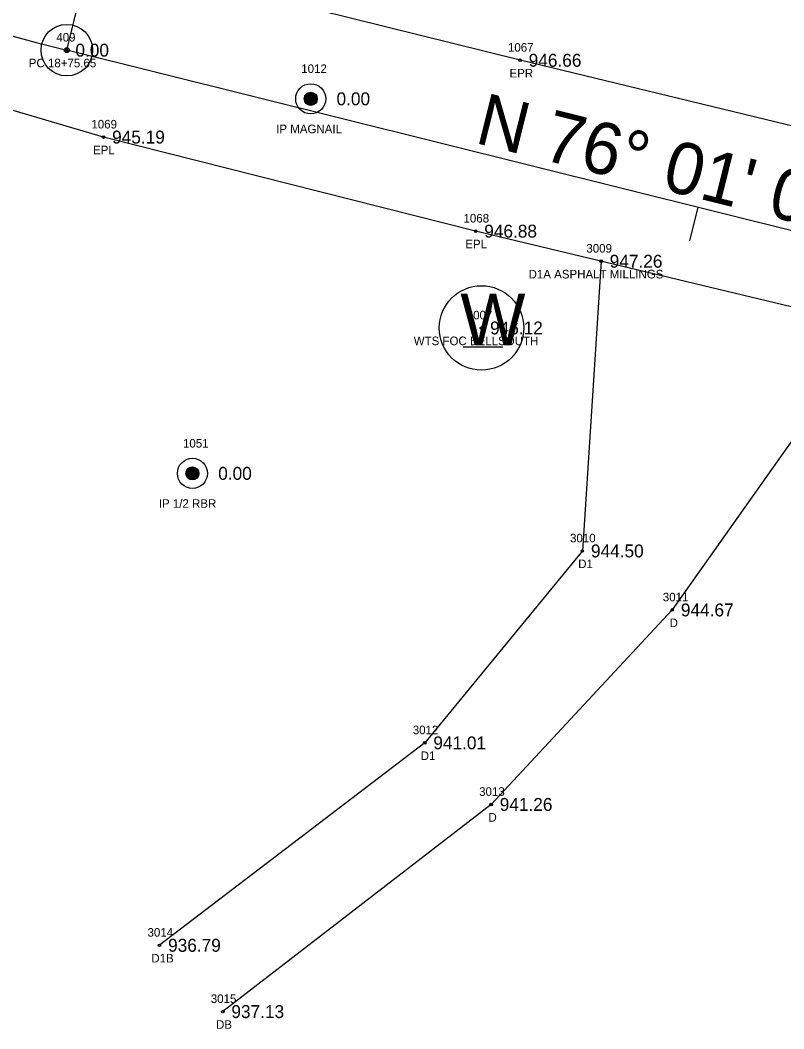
# Model space of a CAD drawing. Extents: x 1528109 to 1531398, y 1157799 to 1162548.
# Drawn here: x 1530236 to 1530324.8, y 1159054.3 to 1159171.6 of the extents above; entities that cross this region are included whole.
import ezdxf

# ---------------------------------------------------------------- set-up
doc = ezdxf.new("R2010")
doc.units = 0
for name, color, linetype in [('RD_EX_Driveway', 7, 'Continuous'), ('RD_EX_Driveway_txCode', 7, 'Continuous'), ('RD_EX_DV_Prop_txCode', 7, 'Continuous'), ('RD_EX_DV_PropPin', 7, 'Continuous'), ('RD_EX_Road', 7, 'Continuous'), ('RD_EX_Road_txCode', 7, 'Continuous'), ('RD_EX_TX_Driveway_ELEV', 7, 'Continuous'), ('RD_EX_TX_DV_Prop_ELEV', 7, 'Continuous'), ('RD_EX_TX_Road_ELEV', 7, 'Continuous'), ('RD_EX_TX_UT_ELEV', 7, 'Continuous'), ('RD_EX_UT', 7, 'Continuous'), ('RD_EX_UT_txCode', 7, 'Continuous'), ('RD_HC_Cl', 7, 'Continuous'), ('RD_HC_Data', 7, 'Continuous'), ('RD_HC_Data_Tic', 7, 'Continuous'), ('RD_HC_Survey_ELEV', 7, 'Continuous'), ('RD_HC_txCode', 7, 'Continuous'), ('RD_SMD_Locator', 7, 'Continuous')]:
    doc.layers.add(name, color=color, linetype=linetype)

msp = doc.modelspace()

# ---------------------------------------------------------------- linework, layer by layer
at = {"layer": 'RD_EX_Driveway'}
for points in [[(1530303.55, 1159143.56), (1530301.37, 1159109.87), (1530283.04, 1159087.55), (1530252.19, 1159064.01)], [(1530335.11, 1159135.94), (1530311.83, 1159103.01), (1530290.76, 1159080.39), (1530259.55, 1159056.3)]]:
    msp.add_lwpolyline(points, dxfattribs=at)
at = {"layer": 'RD_EX_DV_PropPin'}
for p, q in [((1530269.36, 1159161.81), (1530269.36, 1159163.08)), ((1530269.39, 1159161.79), (1530269.39, 1159163.1)), ((1530269.43, 1159161.77), (1530269.43, 1159163.12)), ((1530269.46, 1159161.75), (1530269.46, 1159163.14)), ((1530269.5, 1159161.74), (1530269.5, 1159163.16)), ((1530269.53, 1159161.73), (1530269.53, 1159163.17)), ((1530269.57, 1159161.72), (1530269.57, 1159163.18)), ((1530269.6, 1159161.71), (1530269.6, 1159163.19)), ((1530269.64, 1159161.7), (1530269.64, 1159163.2)), ((1530269.67, 1159161.69), (1530269.67, 1159163.2)), ((1530269.71, 1159161.69), (1530269.71, 1159163.21)), ((1530269.74, 1159161.69), (1530269.74, 1159163.21)), ((1530269.78, 1159161.69), (1530269.78, 1159163.21)), ((1530269.81, 1159161.69), (1530269.81, 1159163.21)), ((1530269.85, 1159161.69), (1530269.85, 1159163.21)), ((1530269.88, 1159161.69), (1530269.88, 1159163.2)), ((1530269.92, 1159161.7), (1530269.92, 1159163.2)), ((1530269.95, 1159161.71), (1530269.95, 1159163.19)), ((1530269.99, 1159161.72), (1530269.99, 1159163.18)), ((1530270.02, 1159161.73), (1530270.02, 1159163.17)), ((1530270.06, 1159161.74), (1530270.06, 1159163.16)), ((1530270.09, 1159161.75), (1530270.09, 1159163.14)), ((1530270.13, 1159161.77), (1530270.13, 1159163.12)), ((1530270.16, 1159161.79), (1530270.16, 1159163.1)), ((1530270.2, 1159161.81), (1530270.2, 1159163.08)), ((1530269.04, 1159162.25), (1530269.04, 1159162.64)), ((1530269.08, 1159162.15), (1530269.08, 1159162.75)), ((1530269.11, 1159162.08), (1530269.11, 1159162.82)), ((1530269.15, 1159162.02), (1530269.15, 1159162.87)), ((1530269.18, 1159161.97), (1530269.18, 1159162.92)), ((1530269.22, 1159161.93), (1530269.22, 1159162.96)), ((1530269.25, 1159161.9), (1530269.25, 1159163)), ((1530269.29, 1159161.87), (1530269.29, 1159163.03)), ((1530269.32, 1159161.84), (1530269.32, 1159163.06)), ((1530270.23, 1159161.84), (1530270.23, 1159163.06)), ((1530270.27, 1159161.87), (1530270.27, 1159163.03)), ((1530270.3, 1159161.9), (1530270.3, 1159163)), ((1530270.34, 1159161.93), (1530270.34, 1159162.96)), ((1530270.37, 1159161.97), (1530270.37, 1159162.92)), ((1530270.41, 1159162.02), (1530270.41, 1159162.87)), ((1530270.44, 1159162.08), (1530270.44, 1159162.82)), ((1530270.48, 1159162.15), (1530270.48, 1159162.75)), ((1530270.51, 1159162.25), (1530270.51, 1159162.64)), ((1530255.29, 1159118.7), (1530255.29, 1159119.09)), ((1530255.32, 1159118.59), (1530255.32, 1159119.19)), ((1530255.36, 1159118.52), (1530255.36, 1159119.26)), ((1530255.39, 1159118.46), (1530255.39, 1159119.32)), ((1530255.43, 1159118.42), (1530255.43, 1159119.37)), ((1530255.46, 1159118.38), (1530255.46, 1159119.41)), ((1530255.5, 1159118.34), (1530255.5, 1159119.44)), ((1530255.53, 1159118.31), (1530255.53, 1159119.47)), ((1530255.57, 1159118.28), (1530255.57, 1159119.5)), ((1530255.6, 1159118.26), (1530255.6, 1159119.53)), ((1530255.64, 1159118.24), (1530255.64, 1159119.55)), ((1530255.67, 1159118.22), (1530255.67, 1159119.57)), ((1530255.71, 1159118.2), (1530255.71, 1159119.58)), ((1530255.74, 1159118.18), (1530255.74, 1159119.6)), ((1530255.78, 1159118.17), (1530255.78, 1159119.61)), ((1530255.81, 1159118.16), (1530255.81, 1159119.62)), ((1530255.85, 1159118.15), (1530255.85, 1159119.63)), ((1530255.88, 1159118.14), (1530255.88, 1159119.64)), ((1530255.92, 1159118.14), (1530255.92, 1159119.65)), ((1530255.95, 1159118.13), (1530255.95, 1159119.65)), ((1530255.99, 1159118.13), (1530255.99, 1159119.65)), ((1530256.02, 1159118.13), (1530256.02, 1159119.65)), ((1530256.06, 1159118.13), (1530256.06, 1159119.65)), ((1530256.09, 1159118.13), (1530256.09, 1159119.65)), ((1530256.13, 1159118.14), (1530256.13, 1159119.65)), ((1530256.16, 1159118.14), (1530256.16, 1159119.64)), ((1530256.2, 1159118.15), (1530256.2, 1159119.63)), ((1530256.23, 1159118.16), (1530256.23, 1159119.62)), ((1530256.27, 1159118.17), (1530256.27, 1159119.61)), ((1530256.3, 1159118.18), (1530256.3, 1159119.6)), ((1530256.34, 1159118.2), (1530256.34, 1159119.58)), ((1530256.37, 1159118.22), (1530256.37, 1159119.57)), ((1530256.41, 1159118.24), (1530256.41, 1159119.55)), ((1530256.44, 1159118.26), (1530256.44, 1159119.53)), ((1530256.48, 1159118.28), (1530256.48, 1159119.5)), ((1530256.51, 1159118.31), (1530256.51, 1159119.47)), ((1530256.55, 1159118.34), (1530256.55, 1159119.44)), ((1530256.58, 1159118.38), (1530256.58, 1159119.41)), ((1530256.62, 1159118.42), (1530256.62, 1159119.37)), ((1530256.65, 1159118.46), (1530256.65, 1159119.32)), ((1530256.69, 1159118.52), (1530256.69, 1159119.26)), ((1530256.72, 1159118.59), (1530256.72, 1159119.19)), ((1530256.76, 1159118.7), (1530256.76, 1159119.09))]:
    msp.add_line(p, q, dxfattribs=at)
for centre, radius in [((1530269.78, 1159162.45), 1.75), ((1530269.78, 1159162.45), 0.761), ((1530256.02, 1159118.89), 1.75), ((1530256.02, 1159118.89), 0.761)]:
    msp.add_circle(centre, radius, dxfattribs=at)
at = {"layer": 'RD_EX_Road'}
for points in [[(1530337.52, 1159156.44), (1530294.13, 1159166.93), (1530250.93, 1159177.7), (1530204.42, 1159191.5), (1530168.45, 1159204.97), (1530120.58, 1159231.54), (1530104.56, 1159243.15), (1530086.77, 1159257.61), (1530051.98, 1159290.88), (1530019.2, 1159326.18), (1529978.15, 1159378.31), (1529959.68, 1159408.2), (1529942.81, 1159442.34), (1529934.79, 1159460.88), (1529923.22, 1159491.09), (1529910.46, 1159527.95), (1529895.99, 1159570.93), (1529881.69, 1159613.98), (1529856.28, 1159690.67), (1529839.74, 1159739.71), (1529819.57, 1159800.04), (1529788.95, 1159890.99)], [(1530332.28, 1159136.67), (1530288.96, 1159147.06), (1530245.68, 1159158), (1530197.52, 1159172.18), (1530159.1, 1159186.57), (1530108.6, 1159214.89), (1530072.67, 1159242.37), (1530037.12, 1159276.96), (1530005.21, 1159311.5), (1529961.59, 1159366.88), (1529941.79, 1159398.29), (1529924.06, 1159434.11), (1529903.77, 1159484.39), (1529891.44, 1159520.8), (1529876.79, 1159564.7), (1529862.9, 1159606.82), (1529836.94, 1159684.29), (1529820.66, 1159733.09), (1529800.02, 1159794.4), (1529769.54, 1159884.46)]]:
    msp.add_lwpolyline(points, dxfattribs=at)
at = {"layer": 'RD_EX_UT'}
msp.add_line((1530287.52, 1159133.59), (1530292.14, 1159133.59), dxfattribs=at)
msp.add_circle((1530289.64, 1159135.8), 4.91, dxfattribs=at)
at = {"layer": 'RD_HC_Cl'}
msp.add_line((1530389.88, 1159131.14), (1530241.41, 1159168.11), dxfattribs=at)
msp.add_arc((1530338.63, 1159558.58), 402.39, 222.8065, 256.0174, dxfattribs=at)
at = {"layer": 'RD_HC_Data'}
msp.add_line((1530241.41, 1159168.11), (1530269.59, 1159281.29), dxfattribs=at)
for radius in [3, 0.282]:
    msp.add_circle((1530241.41, 1159168.11), radius, dxfattribs=at)
at = {"layer": 'RD_HC_Data_Tic'}
msp.add_line((1530314.81, 1159149.83), (1530313.85, 1159145.95), dxfattribs=at)
at = {"layer": 'RD_SMD_Locator'}
for centre in [(1530241.41, 1159168.11), (1530294.13, 1159166.93), (1530269.78, 1159162.45), (1530245.68, 1159158), (1530288.96, 1159147.06), (1530303.55, 1159143.56), (1530289.64, 1159135.8), (1530256.02, 1159118.89), (1530301.37, 1159109.87), (1530311.83, 1159103.01), (1530283.04, 1159087.55), (1530290.76, 1159080.39), (1530252.19, 1159064.01), (1530259.55, 1159056.3)]:
    msp.add_circle(centre, 0.15, dxfattribs=at)

# ---------------------------------------------------------------- texts
at = {"layer": 'RD_EX_Driveway_txCode'}
for s, p in [('3009', (1530301.84, 1159144.56)), ('D1A ASPHALT MILLINGS', (1530295.12, 1159141.56)), ('3010', (1530299.94, 1159110.87)), ('D1', (1530300.89, 1159107.87)), ('3011', (1530310.73, 1159104.01)), ('D', (1530311.52, 1159101.01)), ('3012', (1530281.65, 1159088.55)), ('D1', (1530282.57, 1159085.55)), ('3013', (1530289.37, 1159081.39)), ('D', (1530290.45, 1159078.39)), ('3014', (1530250.8, 1159065.01)), ('D1B', (1530251.24, 1159062.01)), ('3015', (1530258.16, 1159057.3)), ('DB', (1530258.77, 1159054.3))]:
    msp.add_text(s, height=1, dxfattribs=at).set_placement(p)
at = {"layer": 'RD_EX_DV_Prop_txCode'}
for s, p in [('1012', (1530268.68, 1159165.45)), ('IP MAGNAIL', (1530265.76, 1159158.45)), ('1051', (1530254.92, 1159121.89)), ('IP 1/2 RBR', (1530252.11, 1159114.89))]:
    msp.add_text(s, height=1, dxfattribs=at).set_placement(p)
at = {"layer": 'RD_EX_Road_txCode'}
for s, p in [('1067', (1530292.72, 1159167.93)), ('EPR', (1530292.9, 1159164.93)), ('1069', (1530244.27, 1159159)), ('EPL', (1530244.47, 1159156)), ('1068', (1530287.55, 1159148.06)), ('EPL', (1530287.76, 1159145.06))]:
    msp.add_text(s, height=1, dxfattribs=at).set_placement(p)
at = {"layer": 'RD_EX_TX_Driveway_ELEV'}
for s, p in [('947.26', (1530304.55, 1159142.81)), ('944.50', (1530302.37, 1159109.12)), ('944.67', (1530312.83, 1159102.26)), ('941.01', (1530284.04, 1159086.8)), ('941.26', (1530291.76, 1159079.64)), ('936.79', (1530253.19, 1159063.26)), ('937.13', (1530260.55, 1159055.55))]:
    msp.add_text(s, height=1.5, dxfattribs=at).set_placement(p)
at = {"layer": 'RD_EX_TX_DV_Prop_ELEV'}
for p in [(1530272.78, 1159161.7), (1530259.02, 1159118.14)]:
    msp.add_text('0.00', height=1.5, dxfattribs=at).set_placement(p)
at = {"layer": 'RD_EX_TX_Road_ELEV'}
for s, p in [('946.66', (1530295.13, 1159166.18)), ('945.19', (1530246.68, 1159157.25)), ('946.88', (1530289.96, 1159146.31))]:
    msp.add_text(s, height=1.5, dxfattribs=at).set_placement(p)
at = {"layer": 'RD_EX_TX_UT_ELEV'}
msp.add_text('946.12', height=1.5, dxfattribs=at).set_placement((1530290.64, 1159135.05))
at = {"layer": 'RD_EX_UT'}
msp.add_text('W', height=6, dxfattribs=at).set_placement((1530287.18, 1159133.79))
at = {"layer": 'RD_EX_UT_txCode'}
for s, p in [('3007', (1530287.93, 1159136.8)), ('WTS FOC BELLSOUTH', (1530281.76, 1159133.8))]:
    msp.add_text(s, height=1, dxfattribs=at).set_placement(p)
at = {"layer": 'RD_HC_Data'}
msp.add_text('N 76%%d 01\' 03" W', height=6, rotation=346.0174, dxfattribs=at).set_placement((1530288.72, 1159157.36))
at = {"layer": 'RD_HC_Survey_ELEV'}
msp.add_text('0.00', height=1.5, dxfattribs=at).set_placement((1530242.41, 1159167.36))
at = {"layer": 'RD_HC_txCode'}
for s, p in [('409', (1530240.19, 1159169.11)), ('PC 18+75.65', (1530236.99, 1159166.11))]:
    msp.add_text(s, height=1, dxfattribs=at).set_placement(p)

doc.saveas('drawing.dxf')
